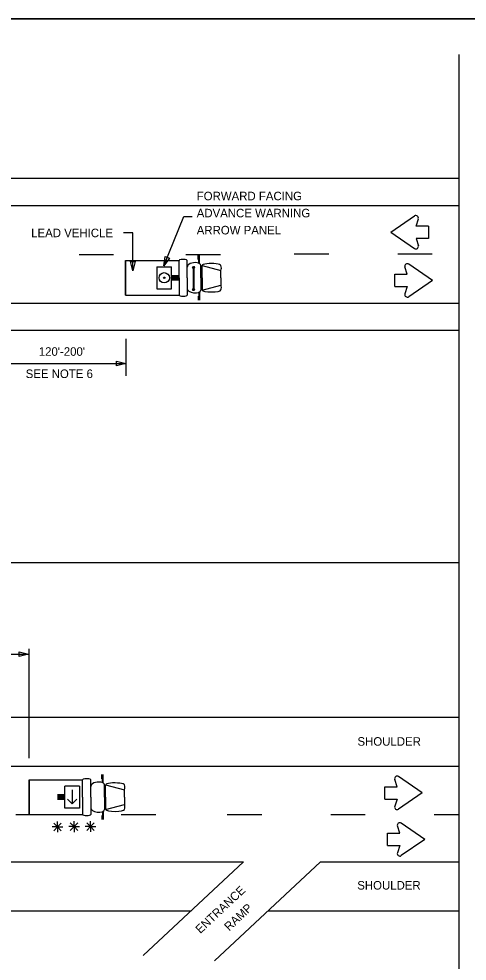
# Model space of a CAD drawing. Extents: x 1374027 to 1374537, y 380415 to 381405.
# Drawn here: x 1374084 to 1374115.5, y 381338.9 to 381405.2 of the extents above; entities that cross this region are included whole.
import ezdxf

# ---------------------------------------------------------------- set-up
doc = ezdxf.new("R2010")
doc.units = 0
doc.layers.add('DSN_DRFT_Junk-No-Plot', color=7, linetype='Continuous')
doc.layers.add('Working Level 1', color=7, linetype='Continuous')

msp = doc.modelspace()

# ---------------------------------------------------------------- linework, layer by layer
at = {"layer": 'DSN_DRFT_Junk-No-Plot'}
for points in [[(1374027.083, 381405.174), (1374197.083, 381405.174), (1374197.083, 381295.174), (1374027.083, 381295.174)], [(1374027.083, 381405.174), (1374027.083, 381295.174), (1374197.083, 381295.174), (1374197.083, 381405.174)]]:
    msp.add_lwpolyline(points, close=True, dxfattribs=at)
at = {"layer": 'Working Level 1'}
for p, q in [((1374114.956, 381402.674), (1374114.956, 381297.674)), ((1374034.976, 381393.968), (1374114.952, 381393.968)), ((1374034.976, 381392.056), (1374114.952, 381392.056)), ((1374110.166, 381390.173), (1374111.833, 381391.316)), ((1374111.938, 381390.609), (1374112.101, 381391.117)), ((1374112.805, 381390.609), (1374111.938, 381390.609)), ((1374112.805, 381390.609), (1374112.805, 381389.736)), ((1374110.166, 381390.173), (1374111.833, 381389.029)), ((1374112.805, 381389.736), (1374111.938, 381389.736)), ((1374111.938, 381389.736), (1374112.101, 381389.229)), ((1374096.633, 381388.258), (1374096.633, 381388.555)), ((1374096.68, 381387.972), (1374096.68, 381388.555)), ((1374096.719, 381387.972), (1374096.719, 381388.555)), ((1374091.527, 381388.186), (1374091.527, 381385.76)), ((1374091.527, 381388.185), (1374095.282, 381388.185)), ((1374091.527, 381385.76), (1374091.527, 381388.185)), ((1374093.733, 381387.749), (1374094.759, 381387.749)), ((1374093.733, 381387.749), (1374093.733, 381386.197)), ((1374094.759, 381386.197), (1374094.759, 381387.749)), ((1374095.282, 381386.973), (1374095.282, 381388.185)), ((1374095.857, 381386.973), (1374095.857, 381388.185)), ((1374096.224, 381387.71), (1374096.224, 381387.71)), ((1374096.286, 381387.675), (1374096.286, 381386.17)), ((1374096.29, 381387.675), (1374096.29, 381386.17)), ((1374096.294, 381387.675), (1374096.294, 381386.17)), ((1374096.302, 381387.675), (1374096.302, 381386.17)), ((1374096.312, 381387.761), (1374096.312, 381387.761)), ((1374096.314, 381387.675), (1374096.314, 381386.17)), ((1374096.821, 381386.973), (1374096.821, 381387.846)), ((1374096.901, 381387.846), (1374098.214, 381387.487)), ((1374096.901, 381386.973), (1374096.901, 381387.846)), ((1374111.322, 381387.224), (1374111.159, 381387.731)), ((1374113.094, 381386.787), (1374111.427, 381387.931)), ((1374094.759, 381387.128), (1374095.282, 381387.128)), ((1374094.759, 381387.05), (1374095.282, 381387.05)), ((1374094.759, 381386.973), (1374095.282, 381386.973)), ((1374095.282, 381386.973), (1374095.282, 381385.76)), ((1374095.857, 381386.973), (1374095.857, 381385.76)), ((1374096.821, 381386.973), (1374096.821, 381386.099)), ((1374096.901, 381386.973), (1374096.901, 381386.099)), ((1374098.214, 381386.973), (1374098.214, 381387.487)), ((1374098.214, 381386.973), (1374098.214, 381386.458)), ((1374110.455, 381386.351), (1374110.455, 381387.224)), ((1374110.455, 381387.224), (1374111.322, 381387.224)), ((1374094.759, 381386.895), (1374095.282, 381386.895)), ((1374094.759, 381386.818), (1374095.282, 381386.818)), ((1374096.901, 381386.099), (1374098.214, 381386.458)), ((1374110.455, 381386.351), (1374111.322, 381386.351)), ((1374111.322, 381386.351), (1374111.159, 381385.844)), ((1374113.094, 381386.787), (1374111.427, 381385.644)), ((1374091.527, 381385.76), (1374095.282, 381385.76)), ((1374093.733, 381386.197), (1374094.759, 381386.197)), ((1374096.228, 381386.157), (1374096.228, 381386.157)), ((1374096.316, 381386.208), (1374096.316, 381386.208)), ((1374096.633, 381385.688), (1374096.633, 381385.391)), ((1374096.68, 381385.973), (1374096.68, 381385.391)), ((1374096.719, 381385.973), (1374096.719, 381385.391)), ((1374034.976, 381385.186), (1374114.952, 381385.186)), ((1374034.976, 381383.298), (1374114.952, 381383.298)), ((1374091.543, 381382.692), (1374091.543, 381380.075)), ((1374083.214, 381380.946), (1374091.543, 381380.946)), ((1374029.583, 381366.948), (1374114.982, 381366.948)), ((1374078.312, 381360.515), (1374084.726, 381360.515)), ((1374084.726, 381360.886), (1374084.726, 381353.197)), ((1374034.976, 381356.094), (1374114.982, 381356.094)), ((1374064.074, 381352.646), (1374114.982, 381352.646)), ((1374089.858, 381351.749), (1374089.858, 381352.046)), ((1374089.905, 381351.464), (1374089.905, 381352.046)), ((1374089.945, 381351.464), (1374089.945, 381352.046)), ((1374112.377, 381350.763), (1374110.71, 381351.906)), ((1374084.753, 381351.677), (1374088.507, 381351.677)), ((1374084.753, 381349.251), (1374084.753, 381351.677)), ((1374084.753, 381351.677), (1374084.753, 381349.252)), ((1374088.287, 381351.24), (1374087.261, 381351.24)), ((1374087.261, 381349.688), (1374087.261, 381351.24)), ((1374088.287, 381351.24), (1374088.287, 381349.688)), ((1374088.507, 381350.464), (1374088.507, 381351.677)), ((1374089.082, 381350.464), (1374089.082, 381351.677)), ((1374090.046, 381350.464), (1374090.046, 381351.338)), ((1374090.126, 381351.338), (1374091.439, 381350.979)), ((1374090.126, 381350.464), (1374090.126, 381351.338)), ((1374109.737, 381350.326), (1374109.737, 381351.199)), ((1374109.737, 381351.199), (1374110.605, 381351.199)), ((1374110.605, 381351.199), (1374110.442, 381351.706)), ((1374087.261, 381350.619), (1374086.738, 381350.619)), ((1374087.261, 381350.541), (1374086.738, 381350.541)), ((1374087.774, 381350.977), (1374087.774, 381349.984)), ((1374091.439, 381350.464), (1374091.439, 381350.979)), ((1374112.377, 381350.763), (1374110.71, 381349.619)), ((1374087.261, 381350.464), (1374086.738, 381350.464)), ((1374087.261, 381350.386), (1374086.738, 381350.386)), ((1374087.261, 381350.309), (1374086.738, 381350.309)), ((1374087.774, 381349.984), (1374087.436, 381350.321)), ((1374087.774, 381349.984), (1374088.103, 381350.313)), ((1374088.507, 381350.464), (1374088.507, 381349.252)), ((1374089.082, 381350.464), (1374089.082, 381349.252)), ((1374090.046, 381350.464), (1374090.046, 381349.591)), ((1374090.126, 381350.464), (1374090.126, 381349.591)), ((1374090.126, 381349.591), (1374091.439, 381349.95)), ((1374091.439, 381350.464), (1374091.439, 381349.95)), ((1374109.737, 381350.326), (1374110.605, 381350.326)), ((1374110.605, 381350.326), (1374110.442, 381349.819)), ((1374084.753, 381349.252), (1374088.507, 381349.252)), ((1374088.287, 381349.688), (1374087.261, 381349.688)), ((1374089.905, 381349.465), (1374089.905, 381348.882)), ((1374089.945, 381349.465), (1374089.945, 381348.882)), ((1374113.218, 381349.247), (1374114.982, 381349.247)), ((1374086.744, 381348.373), (1374086.478, 381348.639)), ((1374086.737, 381348.368), (1374087.004, 381348.634)), ((1374086.744, 381348.373), (1374086.744, 381348.749)), ((1374087.905, 381348.389), (1374087.639, 381348.655)), ((1374087.899, 381348.384), (1374088.165, 381348.65)), ((1374087.905, 381348.389), (1374087.905, 381348.765)), ((1374089.059, 381348.396), (1374088.793, 381348.662)), ((1374089.052, 381348.391), (1374089.319, 381348.657)), ((1374089.059, 381348.396), (1374089.059, 381348.773)), ((1374089.858, 381349.179), (1374089.858, 381348.882)), ((1374112.566, 381347.494), (1374110.899, 381348.638)), ((1374086.744, 381348.373), (1374086.367, 381348.373)), ((1374086.744, 381348.373), (1374086.478, 381348.107)), ((1374086.744, 381348.373), (1374087.01, 381348.107)), ((1374086.744, 381348.373), (1374086.744, 381347.997)), ((1374086.744, 381348.373), (1374087.12, 381348.373)), ((1374087.905, 381348.389), (1374087.529, 381348.389)), ((1374087.905, 381348.389), (1374087.639, 381348.123)), ((1374087.905, 381348.389), (1374088.171, 381348.123)), ((1374087.905, 381348.389), (1374087.905, 381348.013)), ((1374087.905, 381348.389), (1374088.281, 381348.389)), ((1374089.059, 381348.396), (1374088.682, 381348.396)), ((1374089.059, 381348.396), (1374088.793, 381348.13)), ((1374089.059, 381348.396), (1374089.325, 381348.13)), ((1374089.059, 381348.396), (1374089.059, 381348.02)), ((1374089.059, 381348.396), (1374089.435, 381348.396)), ((1374109.926, 381347.058), (1374109.926, 381347.931)), ((1374109.926, 381347.931), (1374110.793, 381347.931)), ((1374110.793, 381347.931), (1374110.63, 381348.438)), ((1374112.566, 381347.494), (1374110.899, 381346.351)), ((1374109.926, 381347.058), (1374110.793, 381347.058)), ((1374110.793, 381347.058), (1374110.63, 381346.55)), ((1374034.976, 381345.924), (1374099.811, 381345.924)), ((1374099.811, 381345.924), (1374092.759, 381339.329)), ((1374105.223, 381345.924), (1374097.775, 381338.96)), ((1374105.223, 381345.924), (1374114.982, 381345.924)), ((1374034.976, 381342.476), (1374096.124, 381342.476)), ((1374101.536, 381342.476), (1374114.982, 381342.476))]:
    msp.add_line(p, q, dxfattribs=at)
for points in [[(1374094.215, 381387.812), (1374095.629, 381391.29), (1374096.207, 381391.29)], [(1374092.035, 381387.457), (1374092.035, 381390.126), (1374091.373, 381390.126)], [(1374088.252, 381388.61), (1374090.678, 381388.61)], [(1374095.765, 381388.61), (1374098.191, 381388.61)], [(1374103.381, 381388.644), (1374105.807, 381388.644)], [(1374110.657, 381388.644), (1374113.082, 381388.644)], [(1374096.222, 381387.684), (1374096.248, 381387.638)], [(1374096.224, 381387.71), (1374096.272, 381387.625)], [(1374096.23, 381387.728), (1374096.291, 381387.622)], [(1374096.239, 381387.742), (1374096.307, 381387.623)], [(1374096.25, 381387.752), (1374096.322, 381387.628)], [(1374096.262, 381387.76), (1374096.334, 381387.634)], [(1374096.276, 381387.764), (1374096.345, 381387.644)], [(1374096.291, 381387.768), (1374096.355, 381387.657)], [(1374096.31, 381387.765), (1374096.362, 381387.673)], [(1374096.331, 381387.757), (1374096.366, 381387.696)], [(1374096.226, 381386.131), (1374096.253, 381386.085)], [(1374096.228, 381386.157), (1374096.277, 381386.072)], [(1374096.234, 381386.175), (1374096.295, 381386.069)], [(1374096.243, 381386.189), (1374096.311, 381386.07)], [(1374096.254, 381386.199), (1374096.326, 381386.075)], [(1374096.266, 381386.207), (1374096.339, 381386.081)], [(1374096.28, 381386.211), (1374096.35, 381386.091)], [(1374096.295, 381386.214), (1374096.359, 381386.104)], [(1374096.314, 381386.212), (1374096.367, 381386.12)], [(1374096.335, 381386.204), (1374096.37, 381386.143)], [(1374083.815, 381349.247), (1374086.241, 381349.247)], [(1374091.223, 381349.247), (1374093.648, 381349.247)], [(1374098.667, 381349.247), (1374101.092, 381349.247)], [(1374105.942, 381349.247), (1374108.368, 381349.247)]]:
    msp.add_lwpolyline(points, dxfattribs=at)
for points in [[(1374094.611, 381388.353), (1374094.215, 381387.812), (1374094.309, 381388.475)], [(1374092.197, 381388.107), (1374092.035, 381387.457), (1374091.872, 381388.107)], [(1374090.893, 381381.108), (1374091.543, 381380.946), (1374090.893, 381380.783)], [(1374084.049, 381360.678), (1374084.699, 381360.515), (1374084.049, 381360.353)]]:
    msp.add_lwpolyline(points, close=True, dxfattribs=at)
for centre, radius in [((1374096.293, 381387.695), 0.0728), ((1374094.246, 381386.973), 0.362), ((1374094.246, 381386.973), 0.0451), ((1374096.298, 381386.142), 0.0728)]:
    msp.add_circle(centre, radius, dxfattribs=at)
for centre, radius, start, end in [((1374111.932, 381391.17), 0.177, 342.18241, 124.44548), ((1374111.932, 381389.175), 0.177, 235.55454, 17.81761), ((1374097.892, 381387.659), 0.364, 331.88006, 28.11991), ((1374111.328, 381387.785), 0.177, 55.55454, 197.81761), ((1374097.892, 381386.287), 0.364, 331.88008, 28.11994), ((1374111.328, 381385.79), 0.177, 162.1824, 304.44547), ((1374110.61, 381351.76), 0.177, 55.55454, 197.81761), ((1374091.118, 381351.15), 0.364, 331.88006, 28.11991), ((1374091.118, 381349.778), 0.364, 331.88008, 28.11994), ((1374110.61, 381349.765), 0.177, 162.1824, 304.44547), ((1374110.799, 381348.492), 0.177, 55.55454, 197.81761), ((1374110.799, 381346.496), 0.177, 162.1824, 304.44547)]:
    msp.add_arc(centre, radius, start, end, dxfattribs=at)
for centre, major_axis, ratio, start_param, end_param in [((1374095.569, 381388.186), (0.288, 0), 0.269913, 0, 3.141593), ((1374096.339, 381387.787), (0.482, 0.06), 0.503092, 0, 3.141593), ((1374097.557, 381387.839), (0.656, -0.008), 0.2034, 0, 3.141593), ((1374095.569, 381385.761), (0.288, 0), 0.269913, 3.141593, 6.283185), ((1374096.339, 381386.159), (0.482, -0.06), 0.503092, 3.141593, 6.283185), ((1374097.557, 381386.107), (0.656, 0.008), 0.2034, 3.141593, 6.283185), ((1374088.795, 381351.677), (0.288, 0), 0.269913, 0, 3.141593), ((1374089.564, 381351.278), (0.482, 0.06), 0.503092, 0, 3.141593), ((1374090.783, 381351.33), (0.656, -0.008), 0.2034, 0, 3.141593), ((1374088.795, 381349.252), (0.288, 0), 0.269913, 3.141593, 6.283185), ((1374089.564, 381349.65), (0.482, -0.06), 0.503092, 3.141593, 6.283185), ((1374090.783, 381349.598), (0.656, 0.008), 0.2034, 3.141593, 6.283185)]:
    msp.add_ellipse(centre, major_axis=major_axis, ratio=ratio, start_param=start_param, end_param=end_param, dxfattribs=at)

# ---------------------------------------------------------------- texts
for s, p in [('FORWARD FACING', (1374096.526, 381392.42)), ('ADVANCE WARNING ', (1374096.526, 381391.22)), ('LEAD VEHICLE', (1374084.892, 381389.826)), ('ARROW PANEL', (1374096.526, 381390.02)), ("120'-200'", (1374085.423, 381381.488)), ('SEE NOTE 6', (1374084.504, 381379.926))]:
    msp.add_text(s, height=0.6, dxfattribs=at).set_placement(p)
for s, rotation, p in [('SHOULDER', 0, (1374107.823, 381354.079)), ('SHOULDER', 0, (1374107.807, 381343.967)), ('ENTRANCE', 43.07908, (1374096.778, 381340.835)), ('RAMP', 43.07908, (1374098.802, 381341.02))]:
    msp.add_text(s, height=0.6, rotation=rotation, dxfattribs=at).set_placement(p)

doc.saveas('drawing.dxf')
